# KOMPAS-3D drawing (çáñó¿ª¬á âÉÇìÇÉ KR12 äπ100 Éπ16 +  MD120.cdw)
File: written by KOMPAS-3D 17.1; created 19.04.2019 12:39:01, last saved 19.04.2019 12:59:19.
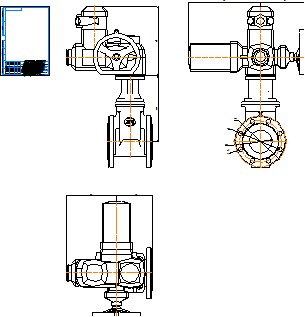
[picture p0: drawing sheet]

Sheet 1: A4, portrait

Title block, sheet 1: name: Задвижка ГРАНАР KR12 Ду100 Ру16 + / MD120; material: Внимание! Данный продукт является объектом авторского права ООО «Торговый Дом АДЛ». / Запрещается изменение, копирование, распространение / (в том числе путем копирования на другие сайты и ресурсы в Интернете) / или любое иное использование информации и объектов без предварительного / согласия правообладателя (ООО «Торговый Дом АДЛ»).; mass: 111,85; sheets: 1; organisation: ООО "Торговый дом АДЛ"; sheet format: A4; stored path: \\adlc.lan\data\АДЛ_ПКД\3D-модели\ADL production\Клиновые задвижки серии KR ГРАНАР\Клиновые задвижки KR12 с эл.приводами Смартгир\KOMPAS 2D\Задвижка ГРАНАР KR12 Ду100 Ру16 +  MD120.cdw

Views: Вид 1, Проекционный вид 3
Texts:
  user
Dimensions and other numbers on the sheet: 282; 299; 220; 180; 214; 153; 1:1; 1; 111,85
